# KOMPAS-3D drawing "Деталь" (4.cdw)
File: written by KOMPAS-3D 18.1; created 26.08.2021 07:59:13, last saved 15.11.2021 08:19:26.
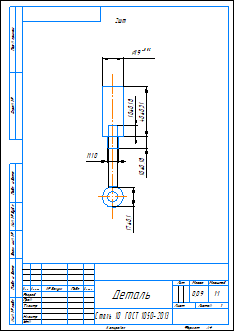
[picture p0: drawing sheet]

Sheet 1: A4, portrait

Document properties: Автор: 111; Масса: 0.0864121; Полное имя файла: ffb\Lii.m3d

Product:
- Part/product: Деталь
    Масса: 0.0864121

Title block, sheet 1: Наименование: Деталь; Материал: Сталь 10  ГОСТ 1050-2013; Масса: 0,09; Количество листов документа: 1; Форматы листов документа: A4; stored path: C:\Users\admin\Desktop\ffb\4.cdw

Views: Вид 1, Спереди
Referenced files in C:\Users\admin\Desktop\ffb\: Lii.m3d
Dimensions and other numbers on the sheet: 19; 40±0,31; 10±0,18; 2шт.; 17±0,1; 1:1; 1; 0,09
